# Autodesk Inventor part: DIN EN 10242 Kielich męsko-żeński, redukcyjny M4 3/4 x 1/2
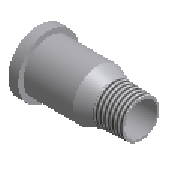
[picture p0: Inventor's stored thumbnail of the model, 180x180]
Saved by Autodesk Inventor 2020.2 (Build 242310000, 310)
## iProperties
Manager: www.cadconsulting.pl
Company: Fabian Stasiak CAD Consulting
NAME: PIPING: DIN EN 10242 Male Female Socket Reducing M4
DATA: <meta><inlinegroups number="1" deflen="3.5"></inlinegroups><connections number="2"></connections><angles><a>3.14159265358979</a></angles></meta>
IsCustomPart: 0
Created: 2014-02
Part Number: DIN EN 10242 Kielich męsko-żeński, redukcyjny M4 3/4 x 1/2
Material: Żelazo, ciągliwe
Description: Kielich
Document SubType Name: Modeling
Standard: DIN EN 10242
Designer: F.Stasiak
Standards Organization: DIN
Language: pl-PL
Size Designation: 3/4 x 1/2
Categories: <MemberInstance><Categories><Category DisplayName="Rury cienko- i grubościenne" InternalName="4347fa0f-2144-441d-94cd-e3e15c92b736" Mnemonic="TUBEANDPIPE"><Cate
Density: 7.15 g/cm^3
Appearance: Częściowo polerowana
Catalog Web Link: www.expertbooks.pl
Author: F.Stasiak
Subject: Zbiór ćwiczeń. Autodesk Inventor 2020. Kurs Professional
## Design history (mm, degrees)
sketch "Sketch1"
  geometry: L1 (0, 0)-(0, 12.059); L2 (0, 12.059)-(0, 16.32); L3 (0, 16.32)-(-5.44, 16.32); L4 (-5.44, 16.32)-(-5.44, 13.6); L5 (-5.44, 13.6)-(-28.26, 13.6); L6 (-28.26, 13.6)-(-34.84, 10.634); L7 (-34.84, 10.634)-(-48, 10.222); L8 (-48, 10.222)-(-48, 9.092); L9 (0, 0)-(-48, 0); L10 (-48, 0)-(-48, 9.092); L11 (-15, 12.059)-(0, 12.059); L12 (-15, 12.059)-(-28.26, 12.058); L13 (-28.26, 12.058)-(-34.84, 9.092); L14 (-34.84, 9.092)-(-48, 9.092); L15 (-28.26, 13.6)-(-28.26, 12.058); L16 (-34.84, 10.634)-(-34.84, 9.092); L17 (-15, 12.059)-(-15, 0); L18 (-34.84, 9.092)-(-34.84, 0); L19 (-39.84, 10.477)-(-39.84, 0)
  constraints: 38 end point, 7 parallel, 7 perpendicular, 4 point on line, 1 collinear, 1 horizontal, 1 vertical
  dimensions: "d0" = 1.78991 deg angle of L9 L7; "d1" = 48 distance of L1.start L9.end (= A); "d2" = 5.44 distance of L2.end L3.end (= EE); "d3" = 13.16 distance of L13.end L8.end (= Z1); "d4" = 33 horizontal distance of L9.end L11.start (= Z); "d6" = 24.117 diameter of L1.end L9 (= MD); "d7" = 27.2 diameter of L4.end L9 (= OD); "d8" = 32.64 diameter of L2.end L9 (= H); "d9" = 6.58 horizontal distance of L5.end L6.end (= 0.5 x Z1); "d17" = 8.16 distance between parallel lines of L8 L19 (= a); "d18" = 20.955 diameter of L19.start L9 (= D1)
revolve "Revolution1" sketch "Sketch1" stored, may be unused: angle "d12" = 90 deg
workpoint "Work Point1"
workpoint "Work Point2"
workaxis "Work Axis1"
workpoint "Work Point3"
workaxis "Work Axis2"
workpoint "Work Point4"
body "Solid1"
feature "Gwint1" dims "d19" = 15 (= A - Z), "d20" = 0
feature "Gwint2" dims "d15" = 10, "d16" = 0
other parameters: "A" = 48 [user parameter; used in 2 equation terms], "OD" = 27.2 [user parameter; used in 3 equation terms], "MD" = 24.117 [user parameter; used in 1 equation term], "Z" = 33 [user parameter; used in 2 equation terms], "Z1" = 13.16 [user parameter; used in 2 equation terms], "EE" = 5.44 (= 0.2 x OD) [user parameter; used in 1 equation term], "H" = 32.64 (= 1.2 x OD) [user parameter; used in 1 equation term], "OD2" = 21.7 [user parameter], "a" = 8.16 [user parameter; used in 1 equation term], "D1" = 20.955 [user parameter; used in 1 equation term], "Size_Designation" = 12.345 [user parameter]
